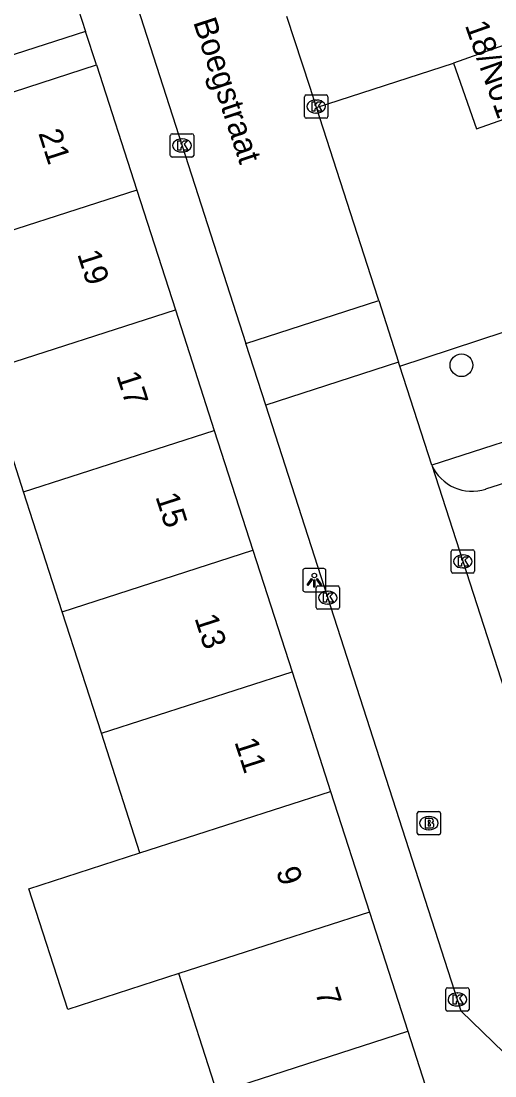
# Model space of a CAD drawing. Extents: x 159377 to 159983, y 382996 to 383595.
# Drawn here: x 159473.09 to 159493.41, y 383280.89 to 383326.11 of the extents above; entities that cross this region are included whole.
import ezdxf

# ---------------------------------------------------------------- set-up
doc = ezdxf.new("R2010")
doc.units = 0
for name, color, linetype in [('IMGEO_Boom', 7, 'Continuous'), ('IMGEO_Brandkraan', 7, 'Continuous'), ('IMGEO_Haag', 7, 'Continuous'), ('IMGEO_Kolk', 7, 'Continuous'), ('IMGEO_Lichtpunt', 7, 'Continuous'), ('IMGEO_Openbare_ruimte_label', 7, 'Continuous'), ('IMGEO_Pand', 7, 'Continuous'), ('IMGEO_Pand_nummerreeks', 7, 'Continuous'), ('IMGEO_Parkeervlak_open', 7, 'Continuous'), ('IMGEO_Rijbaan_lokaal_open', 7, 'Continuous'), ('IMGEO_Voetpad_open', 7, 'Continuous')]:
    doc.layers.add(name, color=color, linetype=linetype)

msp = doc.modelspace()

# ---------------------------------------------------------------- linework, layer by layer
at = {"layer": 'IMGEO_Boom'}
msp.add_circle((159491.974, 383311.355), 0.489, dxfattribs=at)
at = {"layer": 'IMGEO_Brandkraan'}
for p, q in [((159490.076, 383291.297), (159490.076, 383292.149)), ((159490.151, 383292.223), (159491.003, 383292.223)), ((159491.077, 383292.149), (159491.077, 383291.297)), ((159490.564, 383292.003), (159490.589, 383292.003)), ((159490.587, 383291.443), (159490.562, 383291.443)), ((159491.003, 383291.223), (159490.151, 383291.223))]:
    msp.add_line(p, q, dxfattribs=at)
for points in [[(159490.076, 383291.297), (159490.076, 383292.149)], [(159490.151, 383292.223), (159491.003, 383292.223)], [(159491.077, 383292.149), (159491.077, 383291.297)], [(159490.424, 383291.923), (159490.424, 383291.523), (159490.637, 383291.523)], [(159490.655, 383291.923), (159490.424, 383291.923)], [(159490.603, 383291.842), (159490.549, 383291.842), (159490.549, 383291.766)], [(159490.549, 383291.766), (159490.602, 383291.766)], [(159490.611, 383291.69), (159490.549, 383291.69), (159490.549, 383291.609)], [(159490.549, 383291.609), (159490.611, 383291.609)], [(159491.003, 383291.223), (159490.151, 383291.223)]]:
    msp.add_lwpolyline(points, dxfattribs=at)
for centre, radius, start, end in [((159490.153, 383292.147), 0.0765, 91.552, 178.448), ((159490.153, 383292.147), 0.0765, 91.552, 178.448), ((159491.001, 383292.147), 0.0765, 1.552, 88.448), ((159491.001, 383292.147), 0.0765, 1.552, 88.448), ((159490.604, 383291.804), 0.0379, 267.8285, 90.9355), ((159490.659, 383291.778), 0.145, 59.4692, 91.5367), ((159490.684, 383291.825), 0.0922, 285.5137, 58.1501), ((159490.689, 383291.633), 0.105, 301.3115, 78.989), ((159490.153, 383291.299), 0.0765, 181.552, 268.448), ((159490.153, 383291.299), 0.0765, 181.552, 268.448), ((159490.612, 383291.649), 0.0404, 269.8759, 90.5077), ((159490.643, 383291.774), 0.251, 268.6676, 293.5347), ((159491.001, 383291.299), 0.0765, 271.552, 358.448), ((159491.001, 383291.299), 0.0765, 271.552, 358.448)]:
    msp.add_arc(centre, radius, start, end, dxfattribs=at)
for centre, major_axis, ratio, start_param, end_param in [((159490.563, 383291.723), (-0.387, 0.002), 0.722429, 4.712389, 7.853982), ((159490.588, 383291.723), (-0.39, 0.002), 0.717154, 1.570796, 4.712389)]:
    msp.add_ellipse(centre, major_axis=major_axis, ratio=ratio, start_param=start_param, end_param=end_param, dxfattribs=at)
at = {"layer": 'IMGEO_Haag'}
msp.add_lwpolyline([(159496.374, 383308.898), (159490.697, 383307.069)], dxfattribs=at)
at = {"layer": 'IMGEO_Kolk'}
for p, q in [((159485.32, 383322.94), (159486.172, 383322.94)), ((159485.245, 383322.014), (159485.245, 383322.866)), ((159485.733, 383322.72), (159485.758, 383322.72)), ((159486.246, 383322.866), (159486.246, 383322.014)), ((159485.756, 383322.16), (159485.731, 383322.16)), ((159486.172, 383321.94), (159485.32, 383321.94)), ((159479.491, 383320.348), (159479.491, 383321.2)), ((159479.566, 383321.274), (159480.418, 383321.274)), ((159480.492, 383321.2), (159480.492, 383320.348)), ((159479.979, 383321.054), (159480.004, 383321.054)), ((159480.418, 383320.274), (159479.566, 383320.274)), ((159480.002, 383320.494), (159479.977, 383320.494)), ((159491.532, 383302.519), (159491.532, 383303.371)), ((159491.607, 383303.445), (159492.459, 383303.445)), ((159492.02, 383303.225), (159492.045, 383303.225)), ((159492.533, 383303.371), (159492.533, 383302.519)), ((159492.043, 383302.665), (159492.018, 383302.665)), ((159492.459, 383302.445), (159491.607, 383302.445)), ((159485.743, 383300.964), (159485.743, 383301.816)), ((159485.818, 383301.89), (159486.67, 383301.89)), ((159486.231, 383301.67), (159486.256, 383301.67)), ((159486.744, 383301.816), (159486.744, 383300.964)), ((159486.67, 383300.89), (159485.818, 383300.89)), ((159486.254, 383301.11), (159486.229, 383301.11)), ((159491.298, 383283.739), (159491.298, 383284.591)), ((159491.373, 383284.665), (159492.225, 383284.665)), ((159492.299, 383284.591), (159492.299, 383283.739)), ((159491.786, 383284.445), (159491.811, 383284.445)), ((159492.225, 383283.665), (159491.373, 383283.665)), ((159491.809, 383283.885), (159491.784, 383283.885))]:
    msp.add_line(p, q, dxfattribs=at)
for points in [[(159485.32, 383322.94), (159486.172, 383322.94)], [(159485.245, 383322.014), (159485.245, 383322.866)], [(159485.566, 383322.64), (159485.689, 383322.64), (159485.689, 383322.489), (159485.819, 383322.64), (159485.983, 383322.64), (159485.837, 383322.489), (159485.99, 383322.24), (159485.838, 383322.24), (159485.753, 383322.404), (159485.689, 383322.337), (159485.689, 383322.24), (159485.566, 383322.24), (159485.566, 383322.64)], [(159486.246, 383322.866), (159486.246, 383322.014)], [(159486.172, 383321.94), (159485.32, 383321.94)], [(159479.491, 383320.348), (159479.491, 383321.2)], [(159479.566, 383321.274), (159480.418, 383321.274)], [(159480.492, 383321.2), (159480.492, 383320.348)], [(159479.812, 383320.974), (159479.935, 383320.974), (159479.935, 383320.823), (159480.065, 383320.974), (159480.229, 383320.974), (159480.083, 383320.823), (159480.236, 383320.574), (159480.084, 383320.574), (159479.999, 383320.738), (159479.935, 383320.671), (159479.935, 383320.574), (159479.812, 383320.574), (159479.812, 383320.974)], [(159480.418, 383320.274), (159479.566, 383320.274)], [(159491.532, 383302.519), (159491.532, 383303.371)], [(159491.607, 383303.445), (159492.459, 383303.445)], [(159491.853, 383303.145), (159491.976, 383303.145), (159491.976, 383302.994), (159492.106, 383303.145), (159492.27, 383303.145), (159492.124, 383302.994), (159492.277, 383302.745), (159492.125, 383302.745), (159492.04, 383302.909), (159491.976, 383302.842), (159491.976, 383302.745), (159491.853, 383302.745), (159491.853, 383303.145)], [(159492.533, 383303.371), (159492.533, 383302.519)], [(159492.459, 383302.445), (159491.607, 383302.445)], [(159485.743, 383300.964), (159485.743, 383301.816)], [(159485.818, 383301.89), (159486.67, 383301.89)], [(159486.744, 383301.816), (159486.744, 383300.964)], [(159486.064, 383301.59), (159486.187, 383301.59), (159486.187, 383301.439), (159486.317, 383301.59), (159486.481, 383301.59), (159486.335, 383301.439), (159486.488, 383301.19), (159486.336, 383301.19), (159486.251, 383301.354), (159486.187, 383301.287), (159486.187, 383301.19), (159486.064, 383301.19), (159486.064, 383301.59)], [(159486.67, 383300.89), (159485.818, 383300.89)], [(159491.298, 383283.739), (159491.298, 383284.591)], [(159491.373, 383284.665), (159492.225, 383284.665)], [(159492.299, 383284.591), (159492.299, 383283.739)], [(159491.619, 383284.365), (159491.742, 383284.365), (159491.742, 383284.214), (159491.872, 383284.365), (159492.036, 383284.365), (159491.89, 383284.214), (159492.043, 383283.965), (159491.891, 383283.965), (159491.806, 383284.129), (159491.742, 383284.062), (159491.742, 383283.965), (159491.619, 383283.965), (159491.619, 383284.365)], [(159492.225, 383283.665), (159491.373, 383283.665)]]:
    msp.add_lwpolyline(points, dxfattribs=at)
for centre, start, end in [((159485.322, 383322.864), 91.552, 178.448), ((159485.322, 383322.864), 91.552, 178.448), ((159486.17, 383322.864), 1.552, 88.448), ((159486.17, 383322.864), 1.552, 88.448), ((159485.322, 383322.016), 181.552, 268.448), ((159485.322, 383322.016), 181.552, 268.448), ((159486.17, 383322.016), 271.552, 358.448), ((159486.17, 383322.016), 271.552, 358.448), ((159479.568, 383321.198), 91.552, 178.448), ((159479.568, 383321.198), 91.552, 178.448), ((159480.416, 383321.198), 1.552, 88.448), ((159480.416, 383321.198), 1.552, 88.448), ((159479.568, 383320.35), 181.552, 268.448), ((159479.568, 383320.35), 181.552, 268.448), ((159480.416, 383320.35), 271.552, 358.448), ((159480.416, 383320.35), 271.552, 358.448), ((159491.609, 383303.369), 91.552, 178.448), ((159491.609, 383303.369), 91.552, 178.448), ((159492.457, 383303.369), 1.552, 88.448), ((159492.457, 383303.369), 1.552, 88.448), ((159491.609, 383302.521), 181.552, 268.448), ((159491.609, 383302.521), 181.552, 268.448), ((159492.457, 383302.521), 271.552, 358.448), ((159492.457, 383302.521), 271.552, 358.448), ((159485.82, 383301.814), 91.552, 178.448), ((159485.82, 383301.814), 91.552, 178.448), ((159486.668, 383301.814), 1.552, 88.448), ((159486.668, 383301.814), 1.552, 88.448), ((159485.82, 383300.966), 181.552, 268.448), ((159485.82, 383300.966), 181.552, 268.448), ((159486.668, 383300.966), 271.552, 358.448), ((159486.668, 383300.966), 271.552, 358.448), ((159491.375, 383284.589), 91.552, 178.448), ((159491.375, 383284.589), 91.552, 178.448), ((159492.223, 383284.589), 1.552, 88.448), ((159492.223, 383284.589), 1.552, 88.448), ((159491.375, 383283.741), 181.552, 268.448), ((159491.375, 383283.741), 181.552, 268.448), ((159492.223, 383283.741), 271.552, 358.448), ((159492.223, 383283.741), 271.552, 358.448)]:
    msp.add_arc(centre, 0.0765, start, end, dxfattribs=at)
for centre, major_axis, ratio, start_param, end_param in [((159485.732, 383322.44), (-0.387, 0.002), 0.722429, 4.712389, 7.853982), ((159485.757, 383322.44), (-0.39, 0.002), 0.717154, 1.570796, 4.712389), ((159479.978, 383320.774), (-0.387, 0.002), 0.722429, 4.712389, 7.853982), ((159480.003, 383320.774), (-0.39, 0.002), 0.717154, 1.570796, 4.712389), ((159492.019, 383302.945), (-0.387, 0.002), 0.722429, 4.712389, 7.853982), ((159492.044, 383302.945), (-0.39, 0.002), 0.717154, 1.570796, 4.712389), ((159486.23, 383301.39), (-0.387, 0.002), 0.722429, 4.712389, 7.853982), ((159486.255, 383301.39), (-0.39, 0.002), 0.717154, 1.570796, 4.712389), ((159491.785, 383284.165), (-0.387, 0.002), 0.722429, 4.712389, 7.853982), ((159491.81, 383284.165), (-0.39, 0.002), 0.717154, 1.570796, 4.712389)]:
    msp.add_ellipse(centre, major_axis=major_axis, ratio=ratio, start_param=start_param, end_param=end_param, dxfattribs=at)
at = {"layer": 'IMGEO_Lichtpunt'}
for p, q in [((159485.167, 383302.542), (159485.167, 383301.735)), ((159485.167, 383302.542), (159485.167, 383301.735)), ((159486.069, 383302.637), (159485.261, 383302.637)), ((159486.069, 383302.637), (159485.261, 383302.637)), ((159486.163, 383301.735), (159486.163, 383302.542)), ((159486.163, 383301.735), (159486.163, 383302.542)), ((159485.261, 383301.641), (159486.069, 383301.641)), ((159485.261, 383301.641), (159486.069, 383301.641))]:
    msp.add_line(p, q, dxfattribs=at)
for points in [[(159485.541, 383302.206), (159485.58, 383302.178), (159485.392, 383301.916), (159485.354, 383301.943), (159485.541, 383302.206)], [(159485.643, 383302.158), (159485.69, 383302.158), (159485.69, 383301.836), (159485.643, 383301.836), (159485.643, 383302.158)], [(159485.753, 383302.178), (159485.791, 383302.205), (159485.978, 383301.943), (159485.939, 383301.915), (159485.753, 383302.178)]]:
    msp.add_lwpolyline(points, dxfattribs=at)
msp.add_circle((159485.666, 383302.34), 0.0994, dxfattribs=at)
for centre, start, end in [((159485.261, 383302.542), 90, 180), ((159485.261, 383302.542), 90, 180), ((159486.069, 383302.542), 0, 90), ((159486.069, 383302.542), 0, 90), ((159485.261, 383301.735), 180, 270), ((159485.261, 383301.735), 180, 270), ((159486.069, 383301.735), 270, 0), ((159486.069, 383301.735), 270, 360)]:
    msp.add_arc(centre, 0.0946, start, end, dxfattribs=at)
at = {"layer": 'IMGEO_Pand'}
for points in [[(159474.127, 383331.019), (159475.849, 383325.659)], [(159475.849, 383325.659), (159471.091, 383324.124), (159467.69, 383323.026)], [(159495.447, 383322.487), (159494.453, 383325.298), (159491.627, 383324.299)], [(159491.627, 383324.299), (159492.621, 383321.488), (159495.447, 383322.487)], [(159468.153, 383321.575), (159471.572, 383322.687), (159476.326, 383324.233)], [(159476.326, 383324.233), (159478.057, 383318.86)], [(159478.057, 383318.86), (159469.879, 383316.222)], [(159478.057, 383318.86), (159479.71, 383313.73)], [(159471.533, 383311.092), (159479.71, 383313.73)], [(159479.71, 383313.73), (159481.375, 383308.56)], [(159473.199, 383305.922), (159471.533, 383311.092)], [(159473.199, 383305.922), (159481.375, 383308.56)], [(159481.375, 383308.56), (159483.031, 383303.42)], [(159474.856, 383300.783), (159473.199, 383305.922)], [(159474.856, 383300.783), (159483.031, 383303.42)], [(159483.031, 383303.42), (159484.708, 383298.213)], [(159476.535, 383295.576), (159474.856, 383300.783)], [(159476.535, 383295.576), (159484.708, 383298.213)], [(159484.708, 383298.213), (159486.361, 383293.083)], [(159478.188, 383290.446), (159476.535, 383295.576)], [(159478.188, 383290.446), (159486.361, 383293.083)], [(159486.361, 383293.083), (159488.026, 383287.914)], [(159479.855, 383285.277), (159475.096, 383283.742), (159473.429, 383288.911), (159478.188, 383290.446)], [(159488.026, 383287.914), (159479.855, 383285.277)], [(159488.026, 383287.914), (159489.673, 383282.802)], [(159481.503, 383280.166), (159479.855, 383285.277)], [(159481.503, 383280.166), (159489.673, 383282.802)], [(159489.673, 383282.802), (159491.407, 383277.42)]]:
    msp.add_lwpolyline(points, dxfattribs=at)
at = {"layer": 'IMGEO_Parkeervlak_open'}
msp.add_lwpolyline([(159493.019, 383306.048), (159495.816, 383306.937), (159500, 383293.916), (159501.589, 383288.971), (159500, 383288.475), (159498.802, 383288.101)], dxfattribs=at)
msp.add_arc((159492.425, 383307.848), 1.896, 204.2754, 288.2538, dxfattribs=at)
at = {"layer": 'IMGEO_Rijbaan_lokaal_open'}
for points in [[(159462.363, 383367.551), (159464.643, 383368.374), (159482.73, 383312.288)], [(159485.755, 383322.408), (159485.48, 383323.262), (159484.484, 383326.299)], [(159488.424, 383314.124), (159488.383, 383314.25), (159485.755, 383322.408)], [(159482.73, 383312.288), (159488.424, 383314.124)], [(159488.424, 383314.124), (159489.276, 383311.479)], [(159483.583, 383309.643), (159482.73, 383312.288)], [(159489.276, 383311.479), (159483.583, 383309.643)], [(159489.33, 383311.312), (159489.276, 383311.479)], [(159490.697, 383307.069), (159489.33, 383311.312)], [(159497.907, 383277.902), (159491.962, 383283.659), (159483.583, 383309.643)], [(159490.697, 383307.069), (159497.523, 383285.971)]]:
    msp.add_lwpolyline(points, dxfattribs=at)
at = {"layer": 'IMGEO_Voetpad_open'}
for points in [[(159476.326, 383324.233), (159475.849, 383325.659)], [(159485.755, 383322.408), (159491.627, 383324.299)], [(159489.33, 383311.312), (159494.936, 383313.157)]]:
    msp.add_lwpolyline(points, dxfattribs=at)

# ---------------------------------------------------------------- texts
at = {"layer": 'IMGEO_Openbare_ruimte_label'}
msp.add_text('Boegstraat', height=1, rotation=288.1813, dxfattribs=at).set_placement((159480.461, 383326.065))
at = {"layer": 'IMGEO_Pand_nummerreeks'}
for s, rotation, p in [('18/N01', 289.4746, (159492.112, 383325.928)), ('21', 287.8566, (159473.824, 383321.305)), ('19', 287.8566, (159475.492, 383316.125)), ('17', 287.8566, (159477.168, 383310.923)), ('15', 287.8566, (159478.844, 383305.722)), ('13', 287.8566, (159480.519, 383300.52)), ('11', 287.8566, (159482.23, 383295.211)), ('9', 287.8566, (159484.012, 383289.68)), ('7', 287.8566, (159485.687, 383284.479))]:
    msp.add_text(s, height=1, rotation=rotation, dxfattribs=at).set_placement(p)

doc.saveas('drawing.dxf')
